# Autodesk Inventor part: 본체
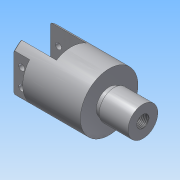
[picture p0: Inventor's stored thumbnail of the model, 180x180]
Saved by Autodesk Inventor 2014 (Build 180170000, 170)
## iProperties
Created: 2019-02
Part Number: 본체
Material: 알루미늄 6061
Document SubType Name: Modeling
Designer: net
Mass: 347.664 g
Surface Area: 292.638 cm^2
Volume: 128.289 cm^3
Density: 2.71 g/cm^3
Appearance: 알루미늄 - 평지
Author: net
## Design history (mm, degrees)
sketch "스케치1"
  geometry: L1 (0, 0)-(38, 0); L2 (0, 29)-(38, 29); L3 (38, 29)-(38, 0); L4 (0, 29)-(0, 14); L5 (0, 14)-(2.65, 14); L6 (2.65, 14)-(2.65, 17); L7 (2.65, 17)-(7.35, 17); L8 (7.35, 17)-(7.35, 14); L9 (7.35, 14)-(11.65, 14); L10 (11.65, 14)-(11.65, 17); L11 (11.65, 17)-(16.35, 17); L12 (16.35, 17)-(16.35, 14); L13 (20, 14)-(20, 16); L14 (20, 16)-(27, 16); L15 (27, 16)-(27, 0); L16 (5, 17)-(5, 0); L17 (14, 17)-(14, 0); L18 (16.35, 14)-(20, 14)
  constraints: 36 end point, 7 parallel, 6 perpendicular, 4 point on line, 3 horizontal alignment, 2 collinear, 2 midpoint, 1 coincident, 1 horizontal, 1 vertical alignment
  dimensions: "d5" = 38 distance of L2.start L2.end; "d7" = 58 diameter of L2 L1; "d8" = 28 diameter of L5 L1; "d9" = 34 diameter of L7 L1; "d11" = 4.7 distance of L6.end L7.end; "d12" = 7 distance of L13.end L14.end; "d15" = 5 horizontal distance of L4.end L16.start; "d16" = 9 distance of L17.start L16.start; "d17" = 32 diameter of L14 L1; "d25" = 27 horizontal distance of L14.end L4.end; "d26" = 29 distance of L2.end L3.end
revolve "회전1" sketch "스케치1" stored, may be unused: angle "d6" = 90 deg
sketch "스케치3"
  geometry: C1 r 29 at (0, 0) reference; C2 r 13 at (0, 0)
  constraints: 1 centre point, 1 coincident
  dimensions: "d19" = 26 diameter of C2
extrude "돌출1" join sketch "스케치3" distance "d20" = 5; taper "d21" = 0 deg
sketch "스케치4"
  geometry: C1 r 13 at (0, 0) reference; C2 r 15 at (0, 0)
  constraints: 1 centre point, 1 coincident
  dimensions: "d22" = 30 diameter of C2
extrude "돌출2" join sketch "스케치4" distance "d23" = 29; taper "d24" = 0 deg
sketch "스케치6"
  geometry: C1 r 29 at (0, 0) reference; C2 r 14 at (0, 0) reference; C3 r 29 at (0, 0)
  constraints: 1 centre point, 1 coincident, 1 concentric
extrude "돌출3" join sketch "스케치6" distance "d27" = 36; taper "d28" = 0 deg
node "작업 평면1"
sketch "스케치7"
  geometry: L1 (-36, 15)-(0, 15); L2 (0, 15)-(0, -15); L3 (0, -15)-(-36, -15); L4 (-36, -15)-(-36, 15); L5 (-36, 29)-(-36, -29) reference; 2 further points
  constraints: 8 end point, 2 parallel, 1 horizontal, 1 horizontal alignment, 1 midpoint, 1 perpendicular, 1 point on line
  dimensions: "d29" = 30 distance of L3.end L1.start; "d30" = 36 distance of L1.start L1.end
extrude "돌출4" cut sketch "스케치7" stored distance "d31" = 36; taper "d32" = 0 deg
sketch "스케치8"
  geometry: L1 (-36, 29)-(-20, 29); L2 (-20, 29)-(-20, 22); L3 (-20, 22)-(-36, 22); L4 (-36, 22)-(-36, 29); L5 (-36, 29)-(-36, 15) reference; L6 (-36, 29)-(38, 29) reference; L7 (-36, -22)-(-20, -22); L8 (-20, -22)-(-20, -29); L9 (-20, -29)-(-36, -29); L10 (-36, -29)-(-36, -22); L11 (-36, -15)-(-36, -29) reference; L12 (-36, -29)-(38, -29) reference; 1 further point
  constraints: 16 end point, 4 parallel, 2 horizontal, 2 perpendicular, 1 collinear
  dimensions: "d33" = 16 distance of L1.start L1.end; "d34" = 16 distance of L9.end L8.end; "d36" = 44 distance of L7.start L3.end
extrude "돌출5" cut sketch "스케치8" stored distance "d37" = 36; taper "d38" = 0 deg
sketch "스케치9"
  geometry: L1 (0, 0)-(16, 0) reference; C1 r 3 at (8, -10.789); C2 r 3 at (8, -28.789); 3 further points
  constraints: 2 centre point, 2 vertical alignment, 1 equal radius, 1 midpoint
  dimensions: "d39" = 6 diameter of C1; "d41" = 9 vertical distance of C2.centre point (0, -37.789); "d42" = 18 distance of C1.centre C2.centre
extrude "돌출6" cut sketch "스케치9" stored distance "d43" = 36; taper "d44" = 0 deg
sketch "스케치10"
  geometry: C1 r 15 at (0, 0) reference
hole "구멍1" sketch "스케치10" at (0, 0) diameter "d46" = 12.376; stored, may be unused: countersink angle "d50" = 90 deg, drill point angle "d52" = 118 deg; dims "d47" = 18, "d48" = 4, "d49" = 2, "d51" = 22
node "작업 평면2"
sketch "스케치11"
  geometry: C1 r 4 at (0, 0); 1 further point
  constraints: 1 centre point, 1 coincident
  dimensions: "d54" = 8 diameter of C1
extrude "돌출7" cut sketch "스케치11" distance "d55" = 23; taper "d56" = 0 deg
node "작업 평면3"
sketch "스케치12"
  geometry: L1 (7, -5)-(-33, -5); L2 (-33, -5)-(-33, 5); L3 (-33, 5)-(7, 5); L4 (7, 5)-(7, -5); L5 (-38, 29)-(-38, -29) reference; 2 further points
  constraints: 8 end point, 2 parallel, 1 horizontal, 1 horizontal alignment, 1 midpoint, 1 perpendicular
  dimensions: "d58" = 10 distance of L3.end L1.start; "d59" = 40 distance of L1.start L1.end; "d60" = 5 distance from line of L5 L1.end
extrude "돌출8" join sketch "스케치12" stored distance "d61" = 23; taper "d62" = 0 deg
node "작업 평면4"
sketch "스케치13"
  geometry: L1 (7, 5)-(7, -5) reference; 2 further points
  constraints: 1 horizontal alignment, 1 other
  dimensions: "d64" = 20 distance from line of point (-13, 0) L1
feature "엠보싱1" sketch "스케치13" dims "d6" = 90 deg, "d65" = 0.5, "d66" = 0
chamfer "모따기1" distance "d67" = 1; stored, may be unused: second distance "d68" = 2, angle "d69" = 45 deg
chamfer "모따기2" distance "d70" = 1; stored, may be unused: second distance "d71" = 2, angle "d72" = 45 deg
fillet "모깎기2" dims "d73" = 0.8
node "솔리드1"
other parameters: "d53" = 27, "d63" = 5
